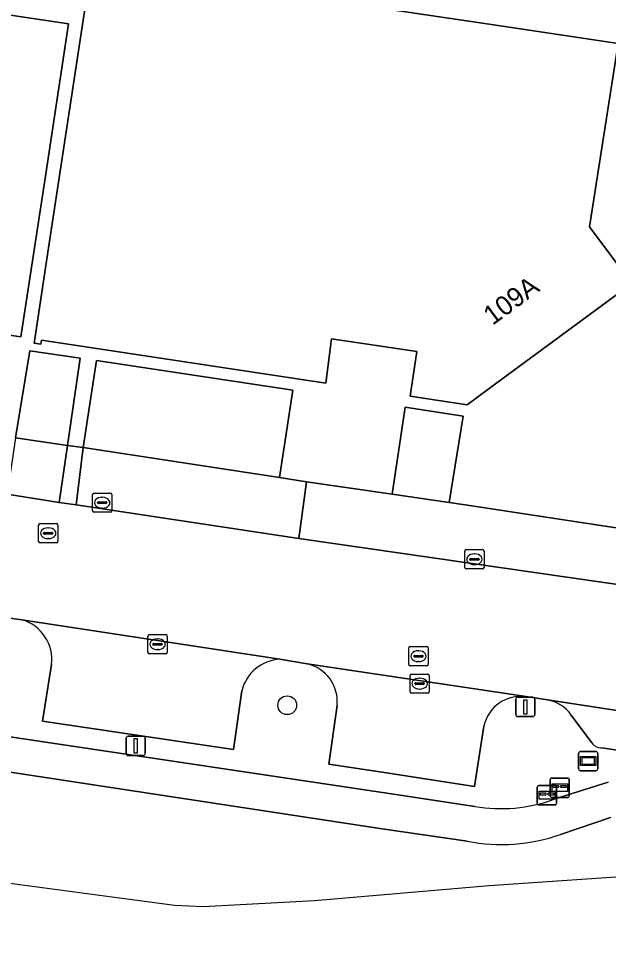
# Model space of a CAD drawing. Extents: x 163008 to 163854, y 382777 to 383982.
# Drawn here: x 163475.57 to 163506.18, y 382814.28 to 382862.95 of the extents above; entities that cross this region are included whole.
import ezdxf

# ---------------------------------------------------------------- set-up
doc = ezdxf.new("R2010")
doc.units = 0
for name, color, linetype in [('IMGEO_Boom', 7, 'Continuous'), ('IMGEO_Brievenbus', 7, 'Continuous'), ('IMGEO_Erf', 7, 'Continuous'), ('IMGEO_Fietspad_open', 7, 'Continuous'), ('IMGEO_Groenvoorziening', 7, 'Continuous'), ('IMGEO_Kolk', 7, 'Continuous'), ('IMGEO_Lichtmast', 7, 'Continuous'), ('IMGEO_Pand', 7, 'Continuous'), ('IMGEO_Pand_nummerreeks', 7, 'Continuous'), ('IMGEO_Parkeervlak_open', 7, 'Continuous'), ('IMGEO_Rijbaan_lokaal_open', 7, 'Continuous'), ('IMGEO_Rioolput', 7, 'Continuous'), ('IMGEO_Straatnaambord', 7, 'Continuous'), ('IMGEO_Voetpad_open', 7, 'Continuous'), ('IMGEO_Waterloop', 7, 'Continuous')]:
    doc.layers.add(name, color=color, linetype=linetype)

msp = doc.modelspace()

# ---------------------------------------------------------------- linework, layer by layer
at = {"layer": 'IMGEO_Boom'}
msp.add_circle((163489.513, 382827.275), 0.489, dxfattribs=at)
at = {"layer": 'IMGEO_Brievenbus'}
for p, q in [((163503.158, 382822.563), (163503.158, 382823.404)), ((163503.158, 382823.404), (163503.158, 382822.563)), ((163503.233, 382823.488), (163504.074, 382823.488)), ((163504.074, 382823.488), (163503.233, 382823.488)), ((163504.158, 382823.413), (163504.158, 382822.572)), ((163504.158, 382822.572), (163504.158, 382823.413)), ((163502.494, 382822.176), (163502.494, 382823.017)), ((163502.494, 382823.017), (163502.494, 382822.176)), ((163502.569, 382823.101), (163503.41, 382823.101)), ((163503.41, 382823.101), (163502.569, 382823.101)), ((163503.602, 382823.095), (163503.325, 382823.095)), ((163503.325, 382823.011), (163503.602, 382823.011)), ((163503.494, 382823.026), (163503.494, 382822.185)), ((163503.494, 382822.185), (163503.494, 382823.026)), ((163503.994, 382823.095), (163503.717, 382823.095)), ((163503.717, 382823.011), (163503.994, 382823.011)), ((163502.938, 382822.708), (163502.661, 382822.708)), ((163502.661, 382822.624), (163502.938, 382822.624)), ((163503.33, 382822.708), (163503.053, 382822.708)), ((163503.053, 382822.624), (163503.33, 382822.624)), ((163504.083, 382822.488), (163503.242, 382822.488)), ((163503.242, 382822.488), (163504.083, 382822.488)), ((163503.419, 382822.101), (163502.578, 382822.101)), ((163502.578, 382822.101), (163503.419, 382822.101))]:
    msp.add_line(p, q, dxfattribs=at)
for points in [[(163503.259, 382823.195), (163504.066, 382823.195), (163504.066, 382822.79), (163503.259, 382822.79), (163503.259, 382823.195)], [(163502.595, 382822.808), (163503.402, 382822.808), (163503.402, 382822.403), (163502.595, 382822.403), (163502.595, 382822.808)]]:
    msp.add_lwpolyline(points, dxfattribs=at)
for centre, radius, start, end in [((163503.236, 382823.41), 0.0779, 92.4484, 184.2845), ((163503.236, 382823.41), 0.0779, 92.4484, 184.2845), ((163504.08, 382823.41), 0.0779, 2.4484, 94.2845), ((163504.08, 382823.41), 0.0779, 2.4484, 94.2845), ((163502.572, 382823.023), 0.0779, 92.4484, 184.2845), ((163502.572, 382823.023), 0.0779, 92.4484, 184.2845), ((163503.355, 382823.053), 0.0519, 125.8089, 234.1911), ((163503.416, 382823.023), 0.0779, 2.4484, 94.2845), ((163503.416, 382823.023), 0.0779, 2.4484, 94.2845), ((163503.571, 382823.053), 0.0519, 305.8089, 54.1911), ((163503.748, 382823.053), 0.0519, 125.8089, 234.1911), ((163503.964, 382823.053), 0.0519, 305.8089, 54.1911), ((163502.691, 382822.666), 0.0519, 125.8089, 234.1911), ((163502.907, 382822.666), 0.0519, 305.8089, 54.1911), ((163503.084, 382822.666), 0.0519, 125.8089, 234.1911), ((163503.236, 382822.566), 0.0779, 182.4484, 274.2845), ((163503.236, 382822.566), 0.0779, 182.4484, 274.2845), ((163503.3, 382822.666), 0.0519, 305.8089, 54.1911), ((163504.08, 382822.566), 0.0779, 272.4484, 4.2845), ((163504.08, 382822.566), 0.0779, 272.4484, 4.2845), ((163502.572, 382822.179), 0.0779, 182.4484, 274.2845), ((163502.572, 382822.179), 0.0779, 182.4484, 274.2845), ((163503.416, 382822.179), 0.0779, 272.4484, 4.2845), ((163503.416, 382822.179), 0.0779, 272.4484, 4.2845)]:
    msp.add_arc(centre, radius, start, end, dxfattribs=at)
at = {"layer": 'IMGEO_Erf'}
for points in [[(163509.643, 382864.012), (163506.726, 382861.854), (163506.696, 382861.663), (163505.214, 382852.135), (163507.397, 382849.187), (163500, 382843.728), (163498.862, 382842.888), (163495.892, 382843.342), (163496.245, 382845.659), (163491.808, 382846.315), (163491.509, 382844.008), (163476.75, 382846.252), (163476.721, 382846.037), (163476.379, 382846.091), (163476.412, 382846.308), (163477.127, 382851.035), (163479.351, 382865.725)], [(163462.188, 382865.086), (163478.166, 382862.686), (163476.928, 382854.545), (163475.691, 382846.414), (163470.141, 382847.231)], [(163475.413, 382841.178), (163476.143, 382845.687), (163478.757, 382845.317), (163478.101, 382840.778), (163478.922, 382840.67), (163479.619, 382845.195), (163489.806, 382843.648), (163489.111, 382839.105), (163490.511, 382838.891), (163494.963, 382838.238), (163495.63, 382842.756), (163498.648, 382842.303), (163497.925, 382837.804), (163498.752, 382837.683), (163508.636, 382836.183)]]:
    msp.add_lwpolyline(points, dxfattribs=at)
at = {"layer": 'IMGEO_Fietspad_open'}
for points in [[(163499.251, 382822.021), (163494.803, 382822.681), (163390.478, 382838.302), (163342.832, 382844.985), (163340.526, 382845.669), (163339.133, 382846.245), (163338.098, 382846.827), (163337.562, 382847.213), (163336.875, 382847.731), (163335.282, 382849.281), (163334.239, 382850.672), (163334.016, 382850.97)], [(163390.211, 382836.499), (163442.533, 382828.767), (163494.45, 382820.86), (163498.854, 382820.217)], [(163506.179, 382823.276), (163503.371, 382822.392)], [(163503.699, 382820.562), (163506.298, 382821.437)]]:
    msp.add_lwpolyline(points, dxfattribs=at)
for centre, radius, start, end in [((163500.621, 382829.869), 7.966, 260.0972, 290.1938), ((163500.647, 382829.235), 9.195, 258.7576, 289.3885)]:
    msp.add_arc(centre, radius, start, end, dxfattribs=at)
at = {"layer": 'IMGEO_Groenvoorziening'}
for points in [[(163334.016, 382850.97), (163334.239, 382850.672), (163335.282, 382849.281), (163336.875, 382847.731), (163337.562, 382847.213), (163338.098, 382846.827), (163339.133, 382846.245), (163340.526, 382845.669), (163342.832, 382844.985), (163390.478, 382838.302), (163494.803, 382822.681), (163499.251, 382822.021)], [(163498.854, 382820.217), (163494.45, 382820.86), (163442.533, 382828.767), (163390.211, 382836.499)], [(163475.736, 382831.717), (163472.515, 382832.16)], [(163490.543, 382829.424), (163489.124, 382829.666)], [(163487.155, 382828.031), (163486.732, 382824.979), (163476.811, 382826.441), (163477.28, 382829.388)], [(163503.022, 382827.548), (163501.914, 382827.724)], [(163407.316, 382827.646), (163421.963, 382825.134), (163483.656, 382816.879), (163485.145, 382816.814), (163490.933, 382817.132), (163500, 382817.915), (163514.398, 382818.897), (163532.552, 382816.044), (163644.684, 382799.5), (163685.451, 382793.218), (163685.611, 382793.195), (163685.611, 382793.195)], [(163499.722, 382826.186), (163499.229, 382823.061), (163494.666, 382823.77), (163491.67, 382824.22), (163492.1, 382827.26)], [(163505.331, 382825.314), (163504.259, 382826.763)], [(163522.288, 382822.539), (163505.845, 382825.06)], [(163503.371, 382822.392), (163506.179, 382823.276)], [(163506.298, 382821.437), (163503.699, 382820.562)]]:
    msp.add_lwpolyline(points, dxfattribs=at)
for centre, radius, start, end in [((163475.134, 382829.642), 2.161, 353.2513, 73.8331), ((163489.254, 382827.506), 2.164, 93.4452, 165.9653), ((163490.125, 382827.481), 1.987, 353.6138, 77.8563), ((163501.651, 382825.767), 1.974, 82.3584, 167.7519), ((163502.705, 382825.681), 1.894, 34.845, 80.3565), ((163505.823, 382825.663), 0.603, 215.3421, 272.0642), ((163500.621, 382829.869), 7.966, 260.0972, 290.1938), ((163500.647, 382829.235), 9.195, 258.7576, 289.3885)]:
    msp.add_arc(centre, radius, start, end, dxfattribs=at)
at = {"layer": 'IMGEO_Kolk'}
for p, q in [((163479.408, 382837.375), (163479.408, 382838.227)), ((163479.483, 382838.301), (163480.335, 382838.301)), ((163479.896, 382838.081), (163479.921, 382838.081)), ((163480.409, 382838.227), (163480.409, 382837.375)), ((163479.667, 382837.795), (163479.667, 382837.807)), ((163480.105, 382837.758), (163479.707, 382837.758)), ((163479.71, 382837.844), (163480.108, 382837.844)), ((163479.919, 382837.521), (163479.894, 382837.521)), ((163480.151, 382837.807), (163480.151, 382837.795)), ((163480.335, 382837.301), (163479.483, 382837.301)), ((163498.729, 382834.436), (163498.729, 382835.288)), ((163498.804, 382835.362), (163499.656, 382835.362)), ((163499.217, 382835.142), (163499.242, 382835.142)), ((163499.73, 382835.288), (163499.73, 382834.436)), ((163498.988, 382834.856), (163498.988, 382834.868)), ((163499.426, 382834.819), (163499.028, 382834.819)), ((163499.031, 382834.905), (163499.429, 382834.905)), ((163499.24, 382834.582), (163499.215, 382834.582)), ((163499.472, 382834.868), (163499.472, 382834.856)), ((163499.656, 382834.362), (163498.804, 382834.362)), ((163482.282, 382830.018), (163482.282, 382830.87)), ((163482.357, 382830.944), (163483.209, 382830.944)), ((163482.77, 382830.724), (163482.795, 382830.724)), ((163483.283, 382830.87), (163483.283, 382830.018)), ((163482.541, 382830.438), (163482.541, 382830.45)), ((163482.979, 382830.401), (163482.581, 382830.401)), ((163482.584, 382830.487), (163482.982, 382830.487)), ((163482.793, 382830.164), (163482.768, 382830.164)), ((163483.025, 382830.45), (163483.025, 382830.438)), ((163483.209, 382829.944), (163482.357, 382829.944)), ((163495.887, 382827.972), (163495.887, 382828.824)), ((163495.962, 382828.898), (163496.814, 382828.898)), ((163496.375, 382828.678), (163496.4, 382828.678)), ((163496.888, 382828.824), (163496.888, 382827.972)), ((163496.146, 382828.392), (163496.146, 382828.404)), ((163496.584, 382828.355), (163496.186, 382828.355)), ((163496.189, 382828.441), (163496.587, 382828.441)), ((163496.63, 382828.404), (163496.63, 382828.392)), ((163496.814, 382827.898), (163495.962, 382827.898)), ((163496.398, 382828.118), (163496.373, 382828.118))]:
    msp.add_line(p, q, dxfattribs=at)
for points in [[(163479.408, 382837.375), (163479.408, 382838.227)], [(163479.483, 382838.301), (163480.335, 382838.301)], [(163480.409, 382838.227), (163480.409, 382837.375)], [(163480.335, 382837.301), (163479.483, 382837.301)], [(163498.729, 382834.436), (163498.729, 382835.288)], [(163498.804, 382835.362), (163499.656, 382835.362)], [(163499.73, 382835.288), (163499.73, 382834.436)], [(163499.656, 382834.362), (163498.804, 382834.362)], [(163482.282, 382830.018), (163482.282, 382830.87)], [(163482.357, 382830.944), (163483.209, 382830.944)], [(163483.283, 382830.87), (163483.283, 382830.018)], [(163483.209, 382829.944), (163482.357, 382829.944)], [(163495.887, 382827.972), (163495.887, 382828.824)], [(163495.962, 382828.898), (163496.814, 382828.898)], [(163496.888, 382828.824), (163496.888, 382827.972)], [(163496.814, 382827.898), (163495.962, 382827.898)]]:
    msp.add_lwpolyline(points, dxfattribs=at)
for centre, radius, start, end in [((163479.485, 382838.225), 0.0765, 91.552, 178.448), ((163479.485, 382838.225), 0.0765, 91.552, 178.448), ((163480.333, 382838.225), 0.0765, 1.552, 88.448), ((163480.333, 382838.225), 0.0765, 1.552, 88.448), ((163479.707, 382837.804), 0.0403, 85.8775, 175.7526), ((163479.704, 382837.794), 0.0366, 178.938, 274.7102), ((163480.108, 382837.801), 0.043, 264.8664, 352.4533), ((163480.112, 382837.806), 0.0386, 1.7309, 96.639), ((163479.485, 382837.377), 0.0765, 181.552, 268.448), ((163479.485, 382837.377), 0.0765, 181.552, 268.448), ((163480.333, 382837.377), 0.0765, 271.552, 358.448), ((163480.333, 382837.377), 0.0765, 271.552, 358.448), ((163498.806, 382835.286), 0.0765, 91.552, 178.448), ((163498.806, 382835.286), 0.0765, 91.552, 178.448), ((163499.654, 382835.286), 0.0765, 1.552, 88.448), ((163499.654, 382835.286), 0.0765, 1.552, 88.448), ((163499.028, 382834.865), 0.0403, 85.8775, 175.7526), ((163499.025, 382834.855), 0.0366, 178.938, 274.7102), ((163499.429, 382834.862), 0.043, 264.8664, 352.4533), ((163499.433, 382834.867), 0.0386, 1.7309, 96.639), ((163498.806, 382834.438), 0.0765, 181.552, 268.448), ((163498.806, 382834.438), 0.0765, 181.552, 268.448), ((163499.654, 382834.438), 0.0765, 271.552, 358.448), ((163499.654, 382834.438), 0.0765, 271.552, 358.448), ((163482.359, 382830.868), 0.0765, 91.552, 178.448), ((163482.359, 382830.868), 0.0765, 91.552, 178.448), ((163483.207, 382830.868), 0.0765, 1.552, 88.448), ((163483.207, 382830.868), 0.0765, 1.552, 88.448), ((163482.581, 382830.447), 0.0403, 85.8775, 175.7526), ((163482.578, 382830.437), 0.0366, 178.938, 274.7102), ((163482.982, 382830.444), 0.043, 264.8664, 352.4533), ((163482.986, 382830.449), 0.0386, 1.7309, 96.639), ((163482.359, 382830.02), 0.0765, 181.552, 268.448), ((163482.359, 382830.02), 0.0765, 181.552, 268.448), ((163483.207, 382830.02), 0.0765, 271.552, 358.448), ((163483.207, 382830.02), 0.0765, 271.552, 358.448), ((163495.964, 382828.822), 0.0765, 91.552, 178.448), ((163495.964, 382828.822), 0.0765, 91.552, 178.448), ((163496.812, 382828.822), 0.0765, 1.552, 88.448), ((163496.812, 382828.822), 0.0765, 1.552, 88.448), ((163496.186, 382828.401), 0.0403, 85.8775, 175.7526), ((163496.183, 382828.391), 0.0366, 178.938, 274.7102), ((163496.587, 382828.398), 0.043, 264.8664, 352.4533), ((163496.591, 382828.403), 0.0386, 1.7309, 96.639), ((163495.964, 382827.974), 0.0765, 181.552, 268.448), ((163495.964, 382827.974), 0.0765, 181.552, 268.448), ((163496.812, 382827.974), 0.0765, 271.552, 358.448), ((163496.812, 382827.974), 0.0765, 271.552, 358.448)]:
    msp.add_arc(centre, radius, start, end, dxfattribs=at)
for centre, major_axis, ratio, start_param, end_param in [((163479.895, 382837.801), (-0.387, 0.002), 0.722429, 4.712389, 7.853982), ((163479.92, 382837.801), (-0.39, 0.002), 0.717154, 1.570796, 4.712389), ((163499.216, 382834.862), (-0.387, 0.002), 0.722429, 4.712389, 7.853982), ((163499.241, 382834.862), (-0.39, 0.002), 0.717154, 1.570796, 4.712389), ((163482.769, 382830.444), (-0.387, 0.002), 0.722429, 4.712389, 7.853982), ((163482.794, 382830.444), (-0.39, 0.002), 0.717154, 1.570796, 4.712389), ((163496.374, 382828.398), (-0.387, 0.002), 0.722429, 4.712389, 7.853982), ((163496.399, 382828.398), (-0.39, 0.002), 0.717154, 1.570796, 4.712389)]:
    msp.add_ellipse(centre, major_axis=major_axis, ratio=ratio, start_param=start_param, end_param=end_param, dxfattribs=at)
at = {"layer": 'IMGEO_Lichtmast'}
for p, q in [((163501.377, 382826.788), (163501.377, 382827.588)), ((163501.377, 382827.588), (163501.377, 382826.788)), ((163501.477, 382827.688), (163502.267, 382827.688)), ((163502.267, 382827.688), (163501.477, 382827.688)), ((163502.367, 382827.588), (163502.367, 382826.788)), ((163502.367, 382826.788), (163502.367, 382827.588)), ((163502.267, 382826.688), (163501.477, 382826.688)), ((163501.477, 382826.688), (163502.267, 382826.688)), ((163481.149, 382824.764), (163481.149, 382825.564)), ((163481.149, 382825.564), (163481.149, 382824.764)), ((163481.249, 382825.664), (163482.039, 382825.664)), ((163482.039, 382825.664), (163481.249, 382825.664)), ((163482.139, 382825.564), (163482.139, 382824.764)), ((163482.139, 382824.764), (163482.139, 382825.564)), ((163482.039, 382824.664), (163481.249, 382824.664)), ((163481.249, 382824.664), (163482.039, 382824.664))]:
    msp.add_line(p, q, dxfattribs=at)
for points in [[(163501.797, 382827.563), (163501.947, 382827.563), (163501.947, 382826.813), (163501.797, 382826.813), (163501.797, 382827.563)], [(163481.569, 382825.539), (163481.719, 382825.539), (163481.719, 382824.789), (163481.569, 382824.789), (163481.569, 382825.539)]]:
    msp.add_lwpolyline(points, dxfattribs=at)
for centre, start, end in [((163501.477, 382827.588), 90, 180), ((163501.477, 382827.588), 90, 180), ((163502.267, 382827.588), 0, 90), ((163502.267, 382827.588), 360, 90), ((163501.477, 382826.788), 180, 270), ((163501.477, 382826.788), 180, 270), ((163502.267, 382826.788), 270, 0), ((163502.267, 382826.788), 270, 0), ((163481.249, 382825.564), 90, 180), ((163481.249, 382825.564), 90, 180), ((163482.039, 382825.564), 0, 90), ((163482.039, 382825.564), 360, 90), ((163481.249, 382824.764), 180, 270), ((163481.249, 382824.764), 180, 270), ((163482.039, 382824.764), 270, 0), ((163482.039, 382824.764), 270, 0)]:
    msp.add_arc(centre, 0.1, start, end, dxfattribs=at)
at = {"layer": 'IMGEO_Pand'}
for points in [[(163481.62, 382880.715), (163479.351, 382865.725), (163500, 382862.658), (163506.696, 382861.663), (163506.726, 382861.854), (163509.643, 382864.012), (163503.215, 382872.767), (163500.912, 382873.106), (163501.607, 382877.746), (163500, 382877.985)], [(163479.351, 382865.725), (163477.127, 382851.035), (163476.412, 382846.308), (163476.379, 382846.091), (163476.721, 382846.037), (163476.75, 382846.252), (163491.509, 382844.008), (163491.808, 382846.315), (163496.245, 382845.659), (163495.892, 382843.342), (163498.862, 382842.888), (163500, 382843.728), (163507.397, 382849.187), (163505.214, 382852.135), (163506.696, 382861.663), (163500, 382862.658)], [(163462.188, 382865.086), (163461.928, 382865.125), (163460.85, 382857.977), (163464.159, 382857.478), (163463.52, 382853.21), (163462.788, 382848.315), (163468.19, 382847.519), (163469.267, 382847.36), (163470.141, 382847.231), (163475.691, 382846.414), (163476.928, 382854.545), (163478.166, 382862.686)]]:
    msp.add_lwpolyline(points, close=True, dxfattribs=at)
at = {"layer": 'IMGEO_Parkeervlak_open'}
for points in [[(163478.757, 382845.317), (163476.143, 382845.687), (163475.413, 382841.178), (163478.101, 382840.778)], [(163489.111, 382839.105), (163489.806, 382843.648), (163479.619, 382845.195), (163478.922, 382840.67)], [(163477.677, 382837.814), (163478.101, 382840.778), (163475.413, 382841.178), (163474.972, 382838.246)], [(163489.111, 382839.105), (163478.922, 382840.67), (163478.557, 382837.692), (163490.123, 382835.931), (163490.511, 382838.891)]]:
    msp.add_lwpolyline(points, close=True, dxfattribs=at)
for points in [[(163489.124, 382829.666), (163475.736, 382831.717)], [(163477.28, 382829.388), (163476.811, 382826.441), (163486.732, 382824.979), (163487.155, 382828.031)], [(163501.914, 382827.724), (163490.543, 382829.424)], [(163492.1, 382827.26), (163491.67, 382824.22), (163494.666, 382823.77), (163499.229, 382823.061), (163499.722, 382826.186)], [(163514.105, 382825.862), (163503.022, 382827.548)], [(163504.259, 382826.763), (163505.331, 382825.314)], [(163505.845, 382825.06), (163522.288, 382822.539)]]:
    msp.add_lwpolyline(points, dxfattribs=at)
for centre, radius, start, end in [((163475.134, 382829.642), 2.161, 353.2513, 73.8331), ((163489.254, 382827.506), 2.164, 93.4452, 165.9653), ((163490.125, 382827.481), 1.987, 353.6138, 77.8563), ((163501.651, 382825.767), 1.974, 82.3584, 167.7519), ((163502.705, 382825.681), 1.894, 34.845, 80.3565), ((163505.823, 382825.663), 0.603, 215.3421, 272.0642)]:
    msp.add_arc(centre, radius, start, end, dxfattribs=at)
at = {"layer": 'IMGEO_Rijbaan_lokaal_open'}
for points in [[(163584.294, 382821.838), (163578.766, 382822.69), (163573.688, 382823.453), (163563.153, 382825.089), (163560.598, 382825.454), (163556.788, 382825.999), (163554.805, 382826.351), (163549.901, 382827.064), (163544.056, 382827.913), (163543.206, 382828.05), (163539.364, 382828.667), (163533.433, 382829.567), (163529.385, 382830.182), (163512.783, 382832.665), (163490.123, 382835.931), (163478.557, 382837.692), (163477.677, 382837.814), (163474.972, 382838.246)], [(163472.515, 382832.16), (163475.736, 382831.717), (163489.124, 382829.666), (163490.543, 382829.424), (163501.914, 382827.724), (163503.022, 382827.548), (163514.105, 382825.862), (163525.71, 382824.122), (163527.258, 382823.873), (163542.74, 382821.554), (163545.478, 382821.145), (163547.367, 382820.84), (163547.53, 382820.816), (163564.547, 382818.255), (163566.771, 382817.917), (163571.05, 382817.267), (163583.274, 382815.396), (163585.042, 382815.141)]]:
    msp.add_lwpolyline(points, dxfattribs=at)
at = {"layer": 'IMGEO_Rioolput'}
for p, q in [((163476.604, 382835.786), (163476.604, 382836.638)), ((163476.679, 382836.712), (163477.531, 382836.712)), ((163477.092, 382836.492), (163477.117, 382836.492)), ((163477.605, 382836.638), (163477.605, 382835.786)), ((163476.863, 382836.206), (163476.863, 382836.218)), ((163477.301, 382836.169), (163476.903, 382836.169)), ((163476.906, 382836.255), (163477.304, 382836.255)), ((163477.347, 382836.218), (163477.347, 382836.206)), ((163477.531, 382835.712), (163476.679, 382835.712)), ((163477.115, 382835.932), (163477.09, 382835.932)), ((163495.826, 382829.398), (163495.826, 382830.25)), ((163495.901, 382830.324), (163496.753, 382830.324)), ((163496.827, 382830.25), (163496.827, 382829.398)), ((163496.085, 382829.818), (163496.085, 382829.83)), ((163496.523, 382829.781), (163496.125, 382829.781)), ((163496.128, 382829.867), (163496.526, 382829.867)), ((163496.314, 382830.104), (163496.339, 382830.104)), ((163496.569, 382829.83), (163496.569, 382829.818)), ((163496.753, 382829.324), (163495.901, 382829.324)), ((163496.337, 382829.544), (163496.312, 382829.544))]:
    msp.add_line(p, q, dxfattribs=at)
for points in [[(163476.604, 382835.786), (163476.604, 382836.638)], [(163476.679, 382836.712), (163477.531, 382836.712)], [(163477.605, 382836.638), (163477.605, 382835.786)], [(163477.531, 382835.712), (163476.679, 382835.712)], [(163495.826, 382829.398), (163495.826, 382830.25)], [(163495.901, 382830.324), (163496.753, 382830.324)], [(163496.827, 382830.25), (163496.827, 382829.398)], [(163496.753, 382829.324), (163495.901, 382829.324)]]:
    msp.add_lwpolyline(points, dxfattribs=at)
for centre, radius, start, end in [((163476.681, 382836.636), 0.0765, 91.552, 178.448), ((163476.681, 382836.636), 0.0765, 91.552, 178.448), ((163477.529, 382836.636), 0.0765, 1.552, 88.448), ((163477.529, 382836.636), 0.0765, 1.552, 88.448), ((163476.903, 382836.215), 0.0403, 85.8775, 175.7526), ((163476.9, 382836.205), 0.0366, 178.938, 274.7102), ((163477.304, 382836.212), 0.043, 264.8664, 352.4533), ((163477.308, 382836.217), 0.0386, 1.7309, 96.639), ((163476.681, 382835.788), 0.0765, 181.552, 268.448), ((163476.681, 382835.788), 0.0765, 181.552, 268.448), ((163477.529, 382835.788), 0.0765, 271.552, 358.448), ((163477.529, 382835.788), 0.0765, 271.552, 358.448), ((163495.903, 382830.248), 0.0765, 91.552, 178.448), ((163495.903, 382830.248), 0.0765, 91.552, 178.448), ((163496.751, 382830.248), 0.0765, 1.552, 88.448), ((163496.751, 382830.248), 0.0765, 1.552, 88.448), ((163496.125, 382829.827), 0.0403, 85.8775, 175.7526), ((163496.122, 382829.817), 0.0366, 178.938, 274.7102), ((163496.526, 382829.824), 0.043, 264.8664, 352.4533), ((163496.53, 382829.829), 0.0386, 1.7309, 96.639), ((163495.903, 382829.4), 0.0765, 181.552, 268.448), ((163495.903, 382829.4), 0.0765, 181.552, 268.448), ((163496.751, 382829.4), 0.0765, 271.552, 358.448), ((163496.751, 382829.4), 0.0765, 271.552, 358.448)]:
    msp.add_arc(centre, radius, start, end, dxfattribs=at)
for centre, major_axis, ratio, start_param, end_param in [((163477.091, 382836.212), (-0.387, 0.002), 0.722429, 4.712389, 7.853982), ((163477.116, 382836.212), (-0.39, 0.002), 0.717154, 1.570796, 4.712389), ((163496.313, 382829.824), (-0.387, 0.002), 0.722429, 4.712389, 7.853982), ((163496.338, 382829.824), (-0.39, 0.002), 0.717154, 1.570796, 4.712389)]:
    msp.add_ellipse(centre, major_axis=major_axis, ratio=ratio, start_param=start_param, end_param=end_param, dxfattribs=at)
at = {"layer": 'IMGEO_Straatnaambord'}
for p, q in [((163504.64, 382823.973), (163504.64, 382824.773)), ((163504.64, 382824.773), (163504.64, 382823.973)), ((163504.74, 382824.873), (163505.53, 382824.873)), ((163505.53, 382824.873), (163504.74, 382824.873)), ((163505.63, 382824.773), (163505.63, 382823.973)), ((163505.63, 382823.973), (163505.63, 382824.773)), ((163505.53, 382823.873), (163504.74, 382823.873)), ((163504.74, 382823.873), (163505.53, 382823.873))]:
    msp.add_line(p, q, dxfattribs=at)
for points in [[(163504.741, 382824.605), (163505.529, 382824.605), (163505.529, 382824.141), (163504.741, 382824.141), (163504.741, 382824.605)], [(163504.806, 382824.54), (163504.806, 382824.206), (163505.464, 382824.206), (163505.464, 382824.54), (163504.806, 382824.54)]]:
    msp.add_lwpolyline(points, dxfattribs=at)
for centre, start, end in [((163504.74, 382824.773), 90, 180), ((163504.74, 382824.773), 90, 180), ((163505.53, 382824.773), 0, 90), ((163505.53, 382824.773), 360, 90), ((163504.74, 382823.973), 180, 270), ((163504.74, 382823.973), 180, 270), ((163505.53, 382823.973), 270, 0), ((163505.53, 382823.973), 270, 0)]:
    msp.add_arc(centre, 0.1, start, end, dxfattribs=at)
at = {"layer": 'IMGEO_Voetpad_open'}
for points in [[(163497.925, 382837.804), (163498.648, 382842.303), (163495.63, 382842.756), (163494.963, 382838.238)], [(163477.677, 382837.814), (163478.557, 382837.692), (163478.922, 382840.67), (163478.101, 382840.778)], [(163508.636, 382836.183), (163498.752, 382837.683), (163497.925, 382837.804), (163494.963, 382838.238), (163490.511, 382838.891), (163490.123, 382835.931), (163512.783, 382832.665), (163529.385, 382830.182), (163529.813, 382832.97), (163519.013, 382834.609)]]:
    msp.add_lwpolyline(points, close=True, dxfattribs=at)
at = {"layer": 'IMGEO_Waterloop'}
msp.add_lwpolyline([(163407.316, 382827.646), (163421.963, 382825.134), (163483.656, 382816.879), (163485.145, 382816.814), (163490.933, 382817.132), (163500, 382817.915), (163514.398, 382818.897), (163532.552, 382816.044), (163644.684, 382799.5), (163685.451, 382793.218), (163685.611, 382793.195), (163685.611, 382793.195)], dxfattribs=at)

# ---------------------------------------------------------------- texts
at = {"layer": 'IMGEO_Pand_nummerreeks'}
msp.add_text('109A', height=1, rotation=36.4281, dxfattribs=at).set_placement((163500.171, 382846.986))

doc.saveas('drawing.dxf')
